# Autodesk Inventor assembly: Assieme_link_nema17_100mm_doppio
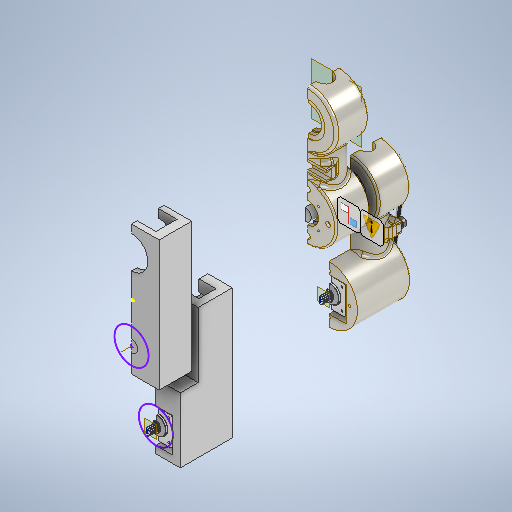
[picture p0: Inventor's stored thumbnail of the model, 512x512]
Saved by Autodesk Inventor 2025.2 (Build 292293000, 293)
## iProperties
Created: 2025-05
Part Number: Assieme_link_nema17_100mm_doppio
Document SubType Name: Assembly
Designer: 18907419
Author: 18907419
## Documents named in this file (16)
- C:\Users\18907419\Desktop\robot v3\Assieme_link_nema17_100mm_doppio.iam
- C:\Users\18907419\Desktop\robot v3\NEMA_14-13mm.iam
- C:\Users\18907419\Desktop\robot v3\gt2-60.ipt
- C:\Users\18907419\Desktop\robot v3\cinghia.ipt
- C:\Users\18907419\Desktop\robot v3\blocco_tendi.ipt
- C:\Users\18907419\Desktop\robot v3\BS 290 SKF - SKF 623.ipt
- C:\Users\18907419\Desktop\robot v3\6705-2RS.ipt
- C:\Users\18907419\Desktop\robot v3\AS 1420 - 1973 - M3 x 6.ipt
- C:\Users\18907419\Desktop\robot v3\blocco_nema17.ipt
- C:\Users\18907419\Desktop\robot v3\blocco_quadrato.ipt
- C:\Users\18907419\Desktop\robot v3\blocco_nema17_intermedio.ipt
- C:\Users\18907419\Desktop\robot v3\gt2-60_base.ipt
- C:\Users\18907419\Desktop\robot v3\link_rettangolare.ipt
- C:\Users\18907419\Desktop\robot v3\link_rettangolare2.ipt
- C:\Users\18907419\Desktop\robot v3\blocco_quadrato_42.ipt
- C:\Users\18907419\Desktop\robot v3\6802-2RS.ipt
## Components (25 placed, 15 different names)
1. blocco_nema17:1
2. NEMA_14HM11-0404S:4 [sub-assembly] — Coincidente:66, Coincidente:67, Coincidente:73, Allineato:15, Coincidente:80
3. cinghia:1 — Coincidente:73, Coincidente:76, Allineato:16
4. blocco_tendi:1 — Allineato:14, Rigido:1, Rotazionale:27, Rigido:2
5. 6705-2RS:3 — Rotazionale:25
6. 6705-2RS:4 — Rotazionale:26, Coincidente:75
7. gt2-60:1
8. BS 290 SKF 623:1 — Rotazionale:27
9. AS 1420 - 1973 - M3 x 6:1 — Rigido:2
10. blocco_quadrato:1 — Coincidente:77, Coincidente:78, Coincidente:82, Angolo:4
11. NEMA_14HM11-0404S:5 [sub-assembly] — Coincidente:79, Angolo:2, Coincidente:80
12. blocco_nema17_intermedio:1 — Angolo:3, Coincidente:82
13. gt2-60_base:2 — Coincidente:84, Coincidente:85
14. gt2-60_base:3 — Coincidente:83, Coincidente:85
15. link_rettangolare:2
16. NEMA_14HM11-0404S:6 [sub-assembly] — Allineato:17, Allineato:18, Coincidente:88, Allineato:19, Allineato:21
17. NEMA_14HM11-0404S:7 [sub-assembly] — Allineato:17, Allineato:18, Allineato:20, Angolo:7
18. gt2-60:2
19. gt2-60_base:4 — Coincidente:90, Allineato:21, Allineato:22, Allineato:23
20. link_rettangolare2:2 — Coincidente:91, Angolo:5, Coincidente:96
21. blocco_quadrato_42:1 — Coincidente:94, Angolo:6, Coincidente:95, Coincidente:96
22. 6705-2RS:5 — Rigido:3
23. 6705-2RS:6 — Rotazionale:28
24. 6802-2RS:1 — Coincidente:98, Allineato:23
25. 6802-2RS:2 — Coincidente:98, Coincidente:99, Allineato:22
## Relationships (44: Mate 21, Flush 10, Angle 6, RevoluteJoint 4, WeldJoint 3)
- Coincidente:66 [Mate]: NEMA_14HM11-0404S:4
- Coincidente:67 [Mate]: NEMA_14HM11-0404S:4
- Allineato:14 [Flush]: blocco_tendi:1
- Rotazionale:25 [RevoluteJoint]: 6705-2RS:3
- Coincidente:73 [Mate]: NEMA_14HM11-0404S:4 ↔ cinghia:1
- Rotazionale:26 [RevoluteJoint]: 6705-2RS:4
- Coincidente:75 [Mate]: 6705-2RS:4
- Allineato:15 [Flush]: NEMA_14HM11-0404S:4
- Coincidente:76 [Mate]: cinghia:1
- Rigido:1 [WeldJoint]: blocco_tendi:1
- Allineato:16 [Flush]: cinghia:1
- Rotazionale:27 [RevoluteJoint]: blocco_tendi:1 ↔ BS 290 SKF 623:1
- Coincidente:77 [Mate]: blocco_quadrato:1
- Coincidente:78 [Mate]: blocco_quadrato:1
- Rigido:2 [WeldJoint]: blocco_tendi:1 ↔ AS 1420 - 1973 - M3 x 6:1
- Coincidente:79 [Mate]: NEMA_14HM11-0404S:5
- Angolo:2 [Angle]: NEMA_14HM11-0404S:5
- Coincidente:80 [Mate]: NEMA_14HM11-0404S:4 ↔ NEMA_14HM11-0404S:5
- Angolo:3 [Angle]: blocco_nema17_intermedio:1
- Coincidente:82 [Mate]: blocco_quadrato:1 ↔ blocco_nema17_intermedio:1
- Angolo:4 [Angle]: blocco_quadrato:1
- Coincidente:83 [Mate]: gt2-60_base:3
- Coincidente:84 [Mate]: gt2-60_base:2
- Coincidente:85 [Mate]: gt2-60_base:2 ↔ gt2-60_base:3
- Allineato:17 [Flush]: NEMA_14HM11-0404S:6 ↔ NEMA_14HM11-0404S:7
- Allineato:18 [Flush]: NEMA_14HM11-0404S:6 ↔ NEMA_14HM11-0404S:7
- Coincidente:88 [Mate]: NEMA_14HM11-0404S:6
- Allineato:19 [Flush]: NEMA_14HM11-0404S:6
- Allineato:20 [Flush]: NEMA_14HM11-0404S:7
- Coincidente:90 [Mate]: gt2-60_base:4
- Coincidente:91 [Mate]: link_rettangolare2:2
- Angolo:5 [Angle]: link_rettangolare2:2
- Allineato:21 [Flush]: NEMA_14HM11-0404S:6 ↔ gt2-60_base:4
- Coincidente:94 [Mate]: blocco_quadrato_42:1
- Angolo:6 [Angle]: blocco_quadrato_42:1
- Coincidente:95 [Mate]: blocco_quadrato_42:1
- Coincidente:96 [Mate]: link_rettangolare2:2 ↔ blocco_quadrato_42:1
- Angolo:7 [Angle]: NEMA_14HM11-0404S:7
- Rigido:3 [WeldJoint]: 6705-2RS:5
- Rotazionale:28 [RevoluteJoint]: 6705-2RS:6
- Coincidente:98 [Mate]: 6802-2RS:1 ↔ 6802-2RS:2
- Coincidente:99 [Mate]: 6802-2RS:2
- Allineato:22 [Flush]: gt2-60_base:4 ↔ 6802-2RS:2
- Allineato:23 [Flush]: gt2-60_base:4 ↔ 6802-2RS:1
